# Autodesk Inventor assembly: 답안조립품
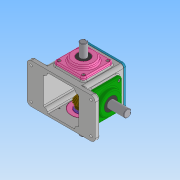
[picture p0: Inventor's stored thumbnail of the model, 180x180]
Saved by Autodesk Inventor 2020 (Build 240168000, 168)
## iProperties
Created: 2021-11
Part Number: 답안조립품
Document SubType Name: Assembly
Designer: user
Mass: 3235.88 g
Surface Area: 2651.66 cm^2
Volume: 866.536 cm^3
Density: 3.73427 g/cm^3
Author: user
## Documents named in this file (16)
- C:\Users\user\Desktop\611112V1005\답안조립품.iam
- C:\Users\user\Desktop\611112V1005\메인커버.ipt
- C:\Users\user\Desktop\611112V1005\베어링 6203.ipt
- C:\Users\user\Desktop\611112V1005\베어링 6204.ipt
- C:\Users\user\Desktop\611112V1005\본체.ipt
- C:\Users\user\Desktop\611112V1005\볼트 M4.ipt
- C:\Users\user\Desktop\611112V1005\상부커버.ipt
- C:\Users\user\Desktop\611112V1005\서브베벨기어.ipt
- C:\Users\user\Desktop\611112V1005\서브축.ipt
- C:\Users\user\Desktop\611112V1005\서브커버.ipt
- C:\Users\user\Desktop\611112V1005\오일 실 17 32 8.ipt
- C:\Users\user\Desktop\611112V1005\오일 실 20 35 8.ipt
- C:\Users\user\Desktop\611112V1005\키 4x4.ipt
- C:\Users\user\Desktop\611112V1005\개스킷.ipt
- C:\Users\user\Desktop\611112V1005\메인베벨기어.ipt
- C:\Users\user\Desktop\611112V1005\메인축.ipt
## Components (1 placed, 1 different names)
1. 개스킷:1
